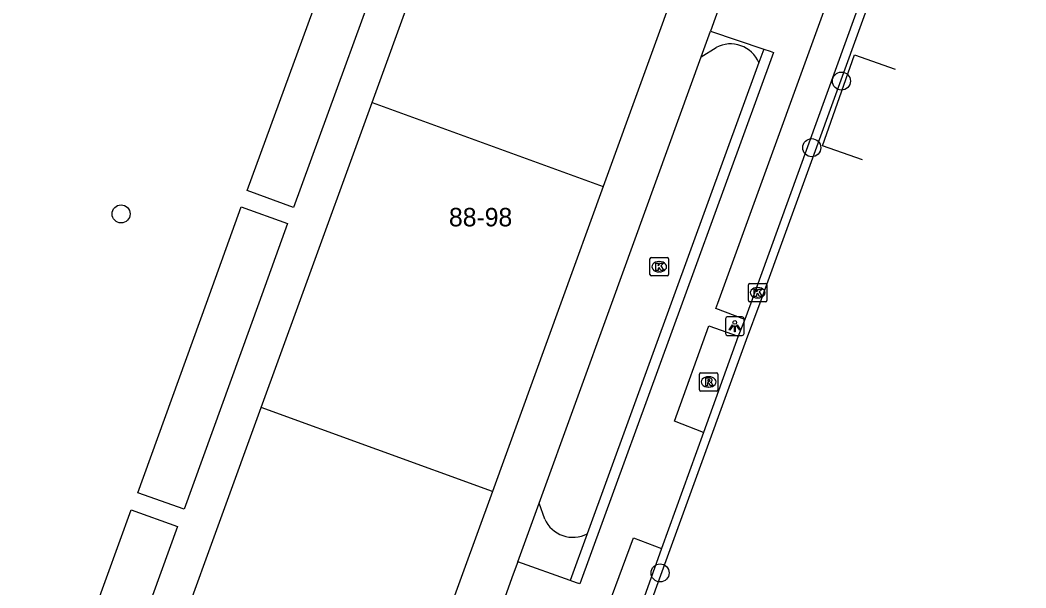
# Model space of a CAD drawing. Extents: x 155888 to 156864, y 383882 to 384671.
# Drawn here: x 156670.9 to 156725.3, y 383984.6 to 384015.3 of the extents above; entities that cross this region are included whole.
import ezdxf

# ---------------------------------------------------------------- set-up
doc = ezdxf.new("R2010")
doc.units = 0
for name, color, linetype in [('IMGEO_Boom', 7, 'Continuous'), ('IMGEO_Greppel_droge_sloot', 7, 'Continuous'), ('IMGEO_Haag', 7, 'Continuous'), ('IMGEO_Kolk', 7, 'Continuous'), ('IMGEO_Lichtpunt', 7, 'Continuous'), ('IMGEO_Pand', 7, 'Continuous'), ('IMGEO_Pand_nummerreeks', 7, 'Continuous'), ('IMGEO_Rijbaan_lokaal_open', 7, 'Continuous'), ('IMGEO_Rioolput', 7, 'Continuous'), ('IMGEO_Voetpad_open', 7, 'Continuous')]:
    doc.layers.add(name, color=color, linetype=linetype)

msp = doc.modelspace()

# ---------------------------------------------------------------- linework, layer by layer
at = {"layer": 'IMGEO_Boom'}
for centre in [(156715.29, 384012), (156713.69, 384008.4), (156676.352, 384004.819), (156705.49, 383985.4)]:
    msp.add_circle(centre, 0.489, dxfattribs=at)
at = {"layer": 'IMGEO_Greppel_droge_sloot'}
for points in [[(156707.707, 384013.313), (156708.522, 384013.824)], [(156710.825, 384013), (156706.16, 384000.188), (156701.548, 383987.518)], [(156699.254, 383988.307), (156698.943, 383989.169)]]:
    msp.add_lwpolyline(points, dxfattribs=at)
for centre, radius, start, end in [((156709.294, 384012.35), 1.663, 22.9879, 117.6383), ((156700.771, 383988.988), 1.662, 204.1643, 297.8754)]:
    msp.add_arc(centre, radius, start, end, dxfattribs=at)
at = {"layer": 'IMGEO_Haag'}
for points in [[(156711.091, 384013.73), (156710.825, 384013)], [(156701.548, 383987.518), (156700.629, 383984.994)]]:
    msp.add_lwpolyline(points, dxfattribs=at)
at = {"layer": 'IMGEO_Kolk'}
for p, q in [((156704.939, 384001.537), (156704.939, 384002.389)), ((156705.014, 384002.463), (156705.866, 384002.463)), ((156705.94, 384002.389), (156705.94, 384001.537)), ((156705.427, 384002.243), (156705.452, 384002.243)), ((156705.866, 384001.463), (156705.014, 384001.463)), ((156705.45, 384001.683), (156705.425, 384001.683)), ((156710.261, 384000.131), (156710.261, 384000.983)), ((156710.336, 384001.057), (156711.188, 384001.057)), ((156710.749, 384000.837), (156710.774, 384000.837)), ((156711.262, 384000.983), (156711.262, 384000.131)), ((156710.772, 384000.277), (156710.747, 384000.277)), ((156711.188, 384000.057), (156710.336, 384000.057))]:
    msp.add_line(p, q, dxfattribs=at)
for points in [[(156704.939, 384001.537), (156704.939, 384002.389)], [(156705.014, 384002.463), (156705.866, 384002.463)], [(156705.94, 384002.389), (156705.94, 384001.537)], [(156705.26, 384002.163), (156705.383, 384002.163), (156705.383, 384002.012), (156705.513, 384002.163), (156705.677, 384002.163), (156705.531, 384002.012), (156705.684, 384001.763), (156705.532, 384001.763), (156705.447, 384001.927), (156705.383, 384001.86), (156705.383, 384001.763), (156705.26, 384001.763), (156705.26, 384002.163)], [(156705.866, 384001.463), (156705.014, 384001.463)], [(156710.261, 384000.131), (156710.261, 384000.983)], [(156710.336, 384001.057), (156711.188, 384001.057)], [(156710.582, 384000.757), (156710.705, 384000.757), (156710.705, 384000.606), (156710.835, 384000.757), (156710.999, 384000.757), (156710.853, 384000.606), (156711.006, 384000.357), (156710.854, 384000.357), (156710.769, 384000.521), (156710.705, 384000.454), (156710.705, 384000.357), (156710.582, 384000.357), (156710.582, 384000.757)], [(156711.262, 384000.983), (156711.262, 384000.131)], [(156711.188, 384000.057), (156710.336, 384000.057)]]:
    msp.add_lwpolyline(points, dxfattribs=at)
for centre, start, end in [((156705.016, 384002.387), 91.552, 178.448), ((156705.016, 384002.387), 91.552, 178.448), ((156705.864, 384002.387), 1.552, 88.448), ((156705.864, 384002.387), 1.552, 88.448), ((156705.016, 384001.539), 181.552, 268.448), ((156705.016, 384001.539), 181.552, 268.448), ((156705.864, 384001.539), 271.552, 358.448), ((156705.864, 384001.539), 271.552, 358.448), ((156710.338, 384000.981), 91.552, 178.448), ((156710.338, 384000.981), 91.552, 178.448), ((156711.186, 384000.981), 1.552, 88.448), ((156711.186, 384000.981), 1.552, 88.448), ((156710.338, 384000.133), 181.552, 268.448), ((156710.338, 384000.133), 181.552, 268.448), ((156711.186, 384000.133), 271.552, 358.448), ((156711.186, 384000.133), 271.552, 358.448)]:
    msp.add_arc(centre, 0.0765, start, end, dxfattribs=at)
for centre, major_axis, ratio, start_param, end_param in [((156705.426, 384001.963), (-0.387, 0.002), 0.722429, 4.712389, 7.853982), ((156705.451, 384001.963), (-0.39, 0.002), 0.717154, 1.570796, 4.712389), ((156710.748, 384000.557), (-0.387, 0.002), 0.722429, 4.712389, 7.853982), ((156710.773, 384000.557), (-0.39, 0.002), 0.717154, 1.570796, 4.712389)]:
    msp.add_ellipse(centre, major_axis=major_axis, ratio=ratio, start_param=start_param, end_param=end_param, dxfattribs=at)
at = {"layer": 'IMGEO_Lichtpunt'}
for p, q in [((156709.029, 383999.15), (156709.029, 383998.343)), ((156709.029, 383999.15), (156709.029, 383998.343)), ((156709.931, 383999.245), (156709.123, 383999.245)), ((156709.931, 383999.245), (156709.123, 383999.245)), ((156710.025, 383998.343), (156710.025, 383999.15)), ((156710.025, 383998.343), (156710.025, 383999.15)), ((156709.123, 383998.249), (156709.931, 383998.249)), ((156709.123, 383998.249), (156709.931, 383998.249))]:
    msp.add_line(p, q, dxfattribs=at)
for points in [[(156709.403, 383998.814), (156709.442, 383998.786), (156709.254, 383998.524), (156709.216, 383998.551), (156709.403, 383998.814)], [(156709.505, 383998.766), (156709.552, 383998.766), (156709.552, 383998.444), (156709.505, 383998.444), (156709.505, 383998.766)], [(156709.615, 383998.786), (156709.653, 383998.813), (156709.84, 383998.551), (156709.801, 383998.523), (156709.615, 383998.786)]]:
    msp.add_lwpolyline(points, dxfattribs=at)
msp.add_circle((156709.528, 383998.948), 0.0994, dxfattribs=at)
for centre, start, end in [((156709.123, 383999.15), 90, 180), ((156709.123, 383999.15), 90, 180), ((156709.931, 383999.15), 0, 90), ((156709.931, 383999.15), 0, 90), ((156709.123, 383998.343), 180, 270), ((156709.123, 383998.343), 180, 270), ((156709.931, 383998.343), 270, 0), ((156709.931, 383998.343), 270, 360)]:
    msp.add_arc(centre, 0.0946, start, end, dxfattribs=at)
at = {"layer": 'IMGEO_Pand'}
for points in [[(156689.919, 384010.845), (156696.47, 384028.869)], [(156708.955, 384024.332), (156702.409, 384006.305)], [(156683.165, 384006.081), (156689.215, 384022.659), (156691.708, 384021.742), (156685.663, 384005.17), (156683.165, 384006.081)], [(156683.925, 383994.35), (156685.978, 384000), (156689.919, 384010.845)], [(156689.919, 384010.845), (156702.409, 384006.305)], [(156702.409, 384006.305), (156700.12, 384000), (156696.42, 383989.808)], [(156680.967, 384000), (156682.85, 384005.197), (156685.341, 384004.294), (156683.791, 384000), (156679.764, 383988.842), (156677.25, 383989.74), (156680.967, 384000)], [(156677.45, 383976.534), (156683.925, 383994.35)], [(156696.42, 383989.808), (156683.925, 383994.35)], [(156696.42, 383989.808), (156689.95, 383971.991)], [(156676.893, 383988.811), (156679.395, 383987.904), (156673.394, 383971.35), (156670.892, 383972.257), (156676.893, 383988.811)]]:
    msp.add_lwpolyline(points, dxfattribs=at)
at = {"layer": 'IMGEO_Rijbaan_lokaal_open'}
for points in [[(156725.263, 384039.726), (156724.824, 384038.423), (156710.873, 384000), (156710.148, 383998.003), (156697.031, 383961.901), (156676.593, 383905.923)], [(156717.572, 384019.8), (156710.389, 384000), (156710.062, 383999.099)], [(156716.432, 384007.739), (156714.276, 384008.493), (156715.998, 384013.414), (156718.193, 384012.646)], [(156710.062, 383999.099), (156709.703, 383998.205)], [(156709.703, 383998.205), (156707.835, 383992.994)], [(156707.835, 383992.994), (156705.569, 383986.715)], [(156705.569, 383986.715), (156703.687, 383981.463)]]:
    msp.add_lwpolyline(points, dxfattribs=at)
at = {"layer": 'IMGEO_Rioolput'}
for p, q in [((156707.612, 383995.305), (156707.612, 383996.157)), ((156707.687, 383996.231), (156708.539, 383996.231)), ((156708.1, 383996.011), (156708.125, 383996.011)), ((156708.613, 383996.157), (156708.613, 383995.305)), ((156708.539, 383995.231), (156707.687, 383995.231)), ((156708.123, 383995.451), (156708.098, 383995.451))]:
    msp.add_line(p, q, dxfattribs=at)
for points in [[(156707.612, 383995.305), (156707.612, 383996.157)], [(156707.687, 383996.231), (156708.539, 383996.231)], [(156708.201, 383995.929), (156707.949, 383995.931), (156707.949, 383995.531)], [(156708.127, 383995.85), (156708.073, 383995.85), (156708.073, 383995.769)], [(156708.073, 383995.769), (156708.125, 383995.769)], [(156708.613, 383996.157), (156708.613, 383995.305)], [(156708.539, 383995.231), (156707.687, 383995.231)], [(156707.949, 383995.531), (156708.073, 383995.531), (156708.073, 383995.693), (156708.084, 383995.693)], [(156708.131, 383995.664), (156708.202, 383995.531), (156708.342, 383995.531), (156708.277, 383995.657)]]:
    msp.add_lwpolyline(points, dxfattribs=at)
for centre, radius, start, end in [((156707.689, 383996.155), 0.0765, 91.552, 178.448), ((156707.689, 383996.155), 0.0765, 91.552, 178.448), ((156708.109, 383995.958), 0.19, 274.7715, 282.9687), ((156708.133, 383995.754), 0.0964, 77.0061, 93.1865), ((156708.147, 383995.811), 0.0378, 276.6634, 79.6772), ((156708.2, 383995.819), 0.109, 350.3612, 89.416), ((156708.198, 383995.819), 0.112, 277.5842, 350.9817), ((156708.537, 383996.155), 0.0765, 1.552, 88.448), ((156708.537, 383996.155), 0.0765, 1.552, 88.448), ((156707.689, 383995.307), 0.0765, 181.552, 268.448), ((156707.689, 383995.307), 0.0765, 181.552, 268.448), ((156708.083, 383995.64), 0.0533, 26.0293, 88.6989), ((156708.182, 383995.604), 0.108, 29.5134, 73.7905), ((156708.537, 383995.307), 0.0765, 271.552, 358.448), ((156708.537, 383995.307), 0.0765, 271.552, 358.448)]:
    msp.add_arc(centre, radius, start, end, dxfattribs=at)
for centre, major_axis, ratio, start_param, end_param in [((156708.099, 383995.731), (-0.387, 0.002), 0.722429, 4.712389, 7.853982), ((156708.124, 383995.731), (-0.39, 0.002), 0.717154, 1.570796, 4.712389)]:
    msp.add_ellipse(centre, major_axis=major_axis, ratio=ratio, start_param=start_param, end_param=end_param, dxfattribs=at)
at = {"layer": 'IMGEO_Voetpad_open'}
for points in [[(156710.062, 383999.099), (156708.5, 383999.702), (156708.608, 384000), (156716.024, 384020.396), (156717.572, 384019.8)], [(156708.889, 384016.571), (156708.211, 384014.702)], [(156707.707, 384013.313), (156708.211, 384014.702)], [(156708.211, 384014.702), (156711.091, 384013.73)], [(156711.091, 384013.73), (156711.437, 384013.613), (156711.612, 384013.554), (156706.677, 384000), (156701.147, 383984.808), (156700.972, 383984.871), (156700.629, 383984.994)], [(156698.943, 383989.169), (156702.875, 384000), (156707.707, 384013.313)], [(156707.835, 383992.994), (156706.268, 383993.61), (156708.118, 383998.773), (156709.703, 383998.205)], [(156697.796, 383986.008), (156698.943, 383989.169)], [(156703.687, 383981.463), (156702.083, 383982.006), (156704.058, 383987.305), (156705.569, 383986.715)], [(156697.796, 383986.008), (156697.553, 383985.338), (156697.031, 383983.874)], [(156700.629, 383984.994), (156697.796, 383986.008)]]:
    msp.add_lwpolyline(points, dxfattribs=at)

# ---------------------------------------------------------------- texts
at = {"layer": 'IMGEO_Pand_nummerreeks'}
msp.add_text('88-98', height=1, dxfattribs=at).set_placement((156694.076, 384004.144))

doc.saveas('drawing.dxf')
